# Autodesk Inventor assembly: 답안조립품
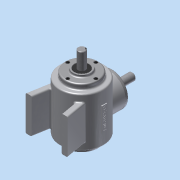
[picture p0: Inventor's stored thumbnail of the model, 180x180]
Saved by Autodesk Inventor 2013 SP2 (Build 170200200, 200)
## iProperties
Created: 2015-01
Part Number: 답안조립품
Document SubType Name: Assembly
Designer: dgall
Author: dgall
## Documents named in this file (15)
- C:\Documents and Settings\dgall\바탕 화면\450105V1027\답안조립품.iam
- C:\Documents and Settings\dgall\바탕 화면\450105V1027\1부품.ipt
- C:\Documents and Settings\dgall\바탕 화면\450105V1027\커버.ipt
- C:\Documents and Settings\dgall\바탕 화면\450105V1027\커버2.ipt
- C:\Documents and Settings\dgall\바탕 화면\450105V1027\M4.ipt
- C:\Documents and Settings\dgall\바탕 화면\450105V1027\서브 축.ipt
- 서브 축.ipt
- C:\Documents and Settings\dgall\바탕 화면\450105V1027\메인 축.ipt
- 메인 축.ipt
- C:\Documents and Settings\dgall\바탕 화면\450105V1027\오일실.ipt
- C:\Documents and Settings\dgall\바탕 화면\450105V1027\키 5x5.ipt
- C:\Documents and Settings\dgall\바탕 화면\450105V1027\키 4x4.ipt
- C:\Documents and Settings\dgall\바탕 화면\450105V1027\메인 베벨기어.ipt
- C:\Documents and Settings\dgall\바탕 화면\450105V1027\서브 베벨기어.ipt
- C:\Documents and Settings\dgall\바탕 화면\450105V1027\베어링 6203.ipt
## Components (13 placed, 2 different names)
1. 1부품:1
2. M4:1
3. M4:6
4. M4:7
5. M4:8
6. M4:9
7. M4:10
8. M4:11
9. M4:12
10. M4:2
11. M4:13
12. M4:14
13. M4:15
